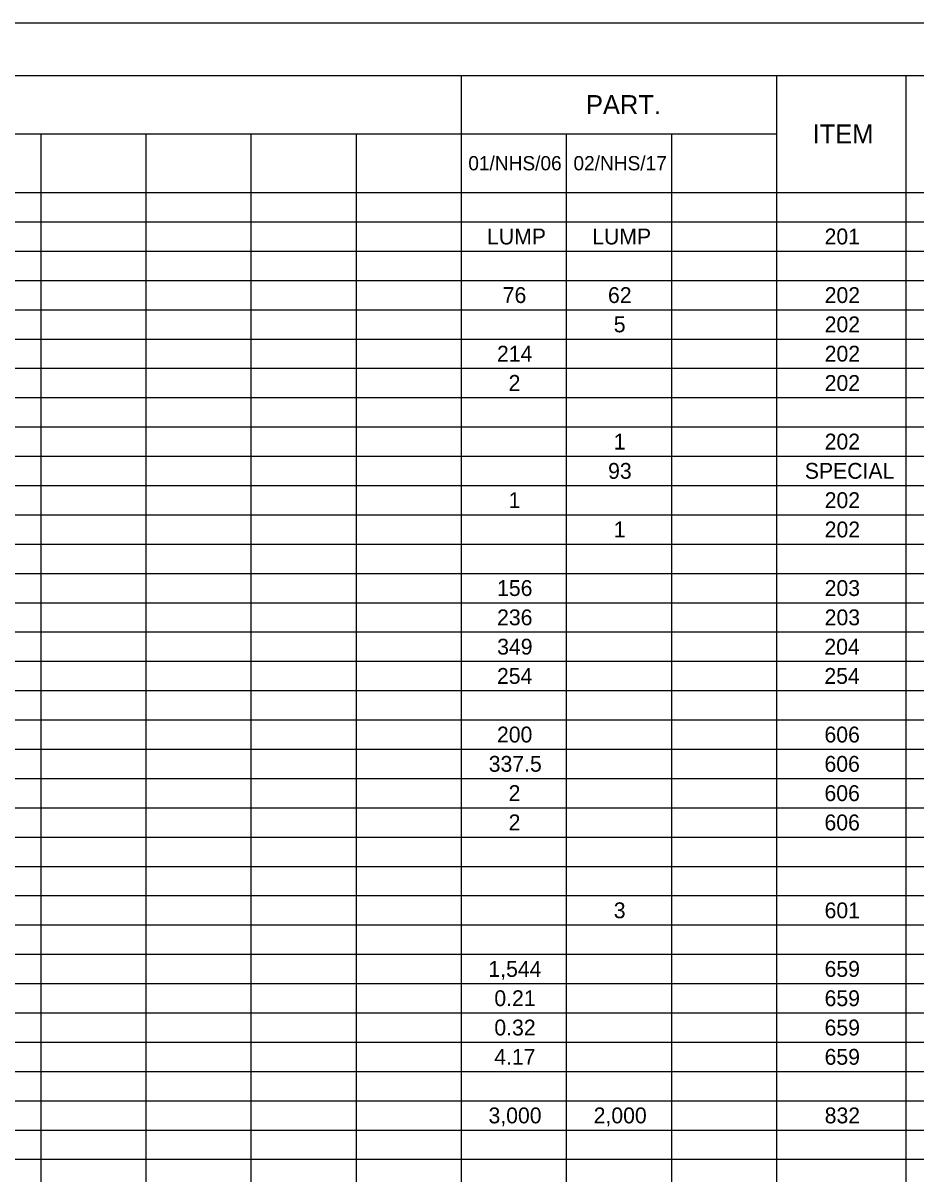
# Model space of a CAD drawing. Extents: x 0 to 34, y 0 to 22.
# Drawn here: x 8.36 to 16.9, y 11 to 22 of the extents above; entities that cross this region are included whole.
import ezdxf

# ---------------------------------------------------------------- set-up
doc = ezdxf.new("R2010")
doc.units = 0
for name, color, linetype in [('Default', 7, 'Continuous'), ('SH_Border', 7, 'Continuous'), ('SH_Cut_Line', 7, 'Continuous')]:
    doc.layers.add(name, color=color, linetype=linetype)

msp = doc.modelspace()

# ---------------------------------------------------------------- linework, layer by layer
at = {"layer": 'Default'}
for p, q in [((1.5, 21.5), (32, 21.5)), ((12.55, 21.5), (12.55, 0.5)), ((15.564, 21.5), (15.564, 0.5)), ((16.799, 21.5), (16.799, 0.5)), ((1.5, 20.94), (15.564, 20.94)), ((8.532, 20.94), (8.532, 0.5)), ((9.537, 20.94), (9.537, 0.5)), ((10.541, 20.94), (10.541, 0.5)), ((11.546, 20.94), (11.546, 0.5)), ((13.555, 20.94), (13.555, 0.5)), ((14.56, 20.94), (14.56, 0.5)), ((1.5, 20.38), (32, 20.38)), ((1.5, 20.1), (32, 20.1)), ((1.5, 19.82), (32, 19.82)), ((1.5, 19.54), (32, 19.54)), ((1.5, 19.26), (32, 19.26)), ((1.5, 18.98), (32, 18.98)), ((1.5, 18.7), (32, 18.7)), ((1.5, 18.42), (32, 18.42)), ((1.5, 18.14), (32, 18.14)), ((1.5, 17.86), (32, 17.86)), ((1.5, 17.58), (32, 17.58)), ((1.5, 17.3), (32, 17.3)), ((1.5, 17.02), (32, 17.02)), ((1.5, 16.74), (32, 16.74)), ((1.5, 16.46), (32, 16.46)), ((1.5, 16.18), (32, 16.18)), ((1.5, 15.9), (32, 15.9)), ((1.5, 15.62), (32, 15.62)), ((1.5, 15.34), (32, 15.34)), ((1.5, 15.06), (32, 15.06)), ((1.5, 14.78), (32, 14.78)), ((1.5, 14.5), (32, 14.5)), ((1.5, 14.22), (32, 14.22)), ((1.5, 13.94), (32, 13.94)), ((1.5, 13.66), (32, 13.66)), ((1.5, 13.38), (32, 13.38)), ((1.5, 13.1), (32, 13.1)), ((1.5, 12.82), (32, 12.82)), ((1.5, 12.54), (32, 12.54)), ((1.5, 12.26), (32, 12.26)), ((1.5, 11.98), (32, 11.98)), ((1.5, 11.7), (32, 11.7)), ((1.5, 11.42), (32, 11.42)), ((1.5, 11.14), (32, 11.14))]:
    msp.add_line(p, q, dxfattribs=at)
at = {"layer": 'SH_Border'}
msp.add_lwpolyline([(1.5, 21.5), (33.5, 21.5), (33.5, 0.5), (1.5, 0.5)], close=True, dxfattribs=at)
at = {"layer": 'SH_Cut_Line'}
msp.add_lwpolyline([(0, 0), (34, 0), (34, 22), (0, 22)], close=True, dxfattribs=at)

# ---------------------------------------------------------------- texts
at = {"layer": 'Default'}
for s, height, p in [('PART.', 0.1818, (13.744, 21.129)), ('ITEM', 0.1818, (15.91, 20.849)), ('01/NHS/06', 0.1364, (12.619, 20.592)), ('02/NHS/17', 0.1364, (13.624, 20.592)), ('LUMP', 0.1515, (12.798, 19.884)), ('LUMP', 0.1515, (13.803, 19.884)), ('201', 0.1515, (16.024, 19.884)), ('76', 0.1515, (12.948, 19.324)), ('62', 0.1515, (13.954, 19.324)), ('202', 0.1515, (16.025, 19.324)), ('5', 0.152, (14.009, 19.044)), ('202', 0.1515, (16.025, 19.044)), ('214', 0.1515, (12.893, 18.764)), ('202', 0.1515, (16.025, 18.764)), ('2', 0.152, (13.004, 18.484)), ('202', 0.1515, (16.025, 18.484)), ('1', 0.152, (14.009, 17.924)), ('202', 0.1515, (16.025, 17.924)), ('93', 0.1515, (13.955, 17.644)), ('SPECIAL', 0.1515, (15.835, 17.644)), ('1', 0.152, (13.004, 17.364)), ('202', 0.1515, (16.025, 17.364)), ('1', 0.152, (14.009, 17.084)), ('202', 0.1515, (16.025, 17.084)), ('156', 0.1515, (12.894, 16.524)), ('203', 0.1515, (16.025, 16.524)), ('236', 0.1515, (12.894, 16.244)), ('203', 0.1515, (16.025, 16.244)), ('349', 0.1515, (12.895, 15.964)), ('204', 0.1515, (16.022, 15.964)), ('254', 0.1515, (12.893, 15.684)), ('254', 0.1515, (16.022, 15.684)), ('200', 0.1515, (12.893, 15.124)), ('606', 0.1515, (16.023, 15.124)), ('337.5', 0.1515, (12.814, 14.844)), ('606', 0.1515, (16.023, 14.844)), ('2', 0.152, (13.004, 14.564)), ('606', 0.1515, (16.023, 14.564)), ('2', 0.152, (13.004, 14.284)), ('606', 0.1515, (16.023, 14.284)), ('3', 0.152, (14.009, 13.444)), ('601', 0.1515, (16.024, 13.444)), ('1,544', 0.1515, (12.811, 12.884)), ('659', 0.1515, (16.024, 12.884)), ('0.21', 0.1515, (12.868, 12.604)), ('659', 0.1515, (16.024, 12.604)), ('0.32', 0.1515, (12.868, 12.324)), ('659', 0.1515, (16.024, 12.324)), ('4.17', 0.1515, (12.867, 12.044)), ('659', 0.1515, (16.024, 12.044)), ('3,000', 0.1515, (12.812, 11.484)), ('2,000', 0.1515, (13.817, 11.484)), ('832', 0.1515, (16.025, 11.484))]:
    msp.add_text(s, height=height, dxfattribs=at).set_placement(p)

doc.saveas('drawing.dxf')
